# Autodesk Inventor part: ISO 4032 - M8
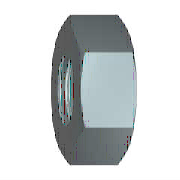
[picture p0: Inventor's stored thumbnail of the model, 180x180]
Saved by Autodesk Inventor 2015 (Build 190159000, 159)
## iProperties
Created: 2014-02
Part Number: ISO 4032 - M8
Material: Aço inoxidável, 440C
Description: Porcas sextavadas, estilo 1 - Produto classes A e B
Document SubType Name: Modeling
Standard: ISO 4032
Designer: Andrew Almeida
Standard Revision: Third edition 1999-08-15
Standards Organization: ISO
Language: pt-BR
Size Designation: M8
Categories: <MemberInstance><Categories><Category DisplayName="Parafusos" InternalName="e4da775c-781d-43d5-af7c-5136215cf5a6" Mnemonic="FSTN"><Category DisplayName="Porcas"
Density: 7.75 g/cm^3
Appearance: Semi-polido
IsCustomPart: 1
Author: Andrew Almeida
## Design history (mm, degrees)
sketch "Rascunho1"
  geometry: L1 (-7.506, 0)-(-3.753, 6.5); L2 (-3.753, 6.5)-(3.753, 6.5); L3 (3.753, 6.5)-(7.506, 0); L4 (7.506, 0)-(3.753, -6.5); L5 (3.753, -6.5)-(-3.753, -6.5); L6 (-3.753, -6.5)-(-7.506, 0); 2 further points
  constraints: 12 end point, 1 coincident, 1 horizontal, 11 other
  dimensions: "d0" = 15.01111 distance of L3.end L1.start (= 1.1547 x SW)
extrude "Corpo" new body sketch "Rascunho1" distance "d1" = 6.8 (= KOH); taper "d2" = 0 deg
sketch "Rascunho2"
  geometry: L1 (0, 3.753)-(0, 7.506) reference; L2 (0, 7.506)-(6.8, 7.506) reference; L3 (6.8, 3.753)-(6.8, 7.506) reference; L4 (-1.36, 0)-(8.16, 0) reference; L5 (0.985, 7.506)-(0, 5.8); L6 (5.815, 7.506)-(6.8, 5.8)
  constraints: 4 end point, 4 point on line
  dimensions: "d3" = 30 deg angle of L1 L5 (= ANG1); "d4" = 30 deg angle of L3 L6 (= ANG2); "d5" = 11.6 diameter of L5.end L4 (= SW0); "d6" = 11.6 diameter of L6.end L4 (= SW01)
revolve "Chanfrar1" sketch "Rascunho2" stored, may be unused: angle "d7" = 90 deg
sketch "Rascunho3"
  geometry: 4 further points
  constraints: 1 coincident, 1 other
hole "Rosca" sketch "Rascunho3" at (0, 0) diameter "d25" = 6.647; stored, may be unused: countersink angle "d29" = 82 deg, drill point angle "d31" = 118 deg; dims "d26" = 6, "d27" = 4, "d28" = 2, "d30" = 8
chamfer "Chanfrar2" distance "d8" = 0.67658 (= -0.5 x GD1 + 0.5 x NND); stored, may be unused: angle "d9" = 30 deg, second distance "d40" = 0.67658 (= -0.5 x GD1 + 0.5 x NND)
chamfer "Chanfrar3" distance "d10" = 0.67658 (= -0.5 x GD1 + 0.5 x NND); stored, may be unused: angle "d11" = 30 deg, second distance "d41" = 0.67658 (= -0.5 x GD1 + 0.5 x NND)
workaxis "Work Axis1"
workplane "Work Plane1"
body "Solid1"
other parameters: "ANG1" = 30 deg [user parameter; used in 1 equation term], "ANG2" = 30 deg [user parameter; used in 1 equation term], "NND" = 8 [user parameter; used in 4 equation terms], "KOH" = 6.8 [user parameter; used in 1 equation term], "SW" = 13 [user parameter; used in 2 equation terms], "SW0" = 11.6 [user parameter; used in 2 equation terms], "SW01" = 11.6 (= SW0) [user parameter; used in 1 equation term], "GD1" = 6.64684 (computed from THREADDIA, PTC, TOA) [user parameter; used in 4 equation terms], "d13" = 0, "d14" = 0, "d39" = 0, "d42" = 0, "GUL" = 0.67658 (= 0.541266 x PTC) [user parameter], "TPU" = 8 (computed from PTC) [user parameter], "THREADDIA" = 8 [user parameter; used in 1 equation term], "TOA" = 30 deg [user parameter; used in 1 equation term], "PTC" = 1.25 [user parameter; used in 4 equation terms], "E0" = 15.015 (= 1.155 x SW) [user parameter], "GAL" = 0.67658 (= 0.541266 x PTC) [user parameter]
